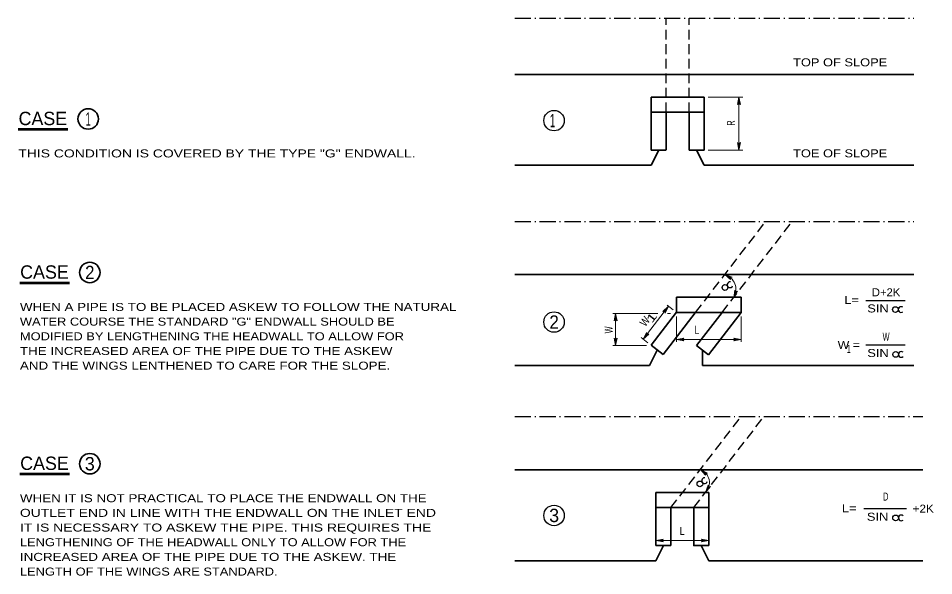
# Model space of a CAD drawing. Extents: x 134 to 247, y -59 to 103.
# Drawn here: x 133.6 to 246.8, y 34.2 to 103.1 of the extents above; entities that cross this region are included whole.
import ezdxf
from ezdxf.enums import TextEntityAlignment as Align

# ---------------------------------------------------------------- set-up
doc = ezdxf.new("R2010")
doc.units = 0
doc.header["$LTSCALE"] = 0.4
doc.linetypes.add('DOT_DASHED', pattern=[7.7, 5, -1.2, 0.3, -1.2])
doc.linetypes.add('MEDIUM_DASHED', pattern=[4.5, 3, -1.5])
for name, color, linetype, lineweight in [('1', 7, 'Continuous', 35), ('10', 7, 'Continuous', 13), ('13', 7, 'Continuous', 53)]:
    doc.layers.add(name, color=color, linetype=linetype, lineweight=lineweight)
doc.layers.add('12', color=7, linetype='Continuous')

msp = doc.modelspace()

# ---------------------------------------------------------------- linework, layer by layer
at = {"layer": '1', "linetype": 'DOT_DASHED', "lineweight": 25}
for p, q in [((194.9967, 103.1357), (244.3561, 103.1357)), ((194.9967, 78.0264), (244.3561, 78.0264)), ((194.9967, 53.876), (245.4598, 53.876))]:
    msp.add_line(p, q, dxfattribs=at)
at = {"layer": '1', "linetype": 'MEDIUM_DASHED', "lineweight": 25}
for p, q in [((213.7467, 91.5186), (213.7467, 103.1357)), ((216.5592, 91.5186), (216.5592, 103.1357)), ((217.3504, 66.7439), (226.0509, 78.0264)), ((220.6394, 66.7439), (229.3399, 78.0264)), ((214.324, 42.626), (223.0245, 53.9086)), ((217.1365, 42.626), (225.837, 53.9086))]:
    msp.add_line(p, q, dxfattribs=at)
at = {"layer": '1'}
for p, q in [((194.9967, 96.2061), (244.3561, 96.2061)), ((211.8717, 93.3936), (218.4342, 93.3936)), ((211.8717, 93.3936), (211.8717, 86.8311)), ((218.4342, 93.3936), (218.4342, 86.8311)), ((211.8717, 91.5186), (218.4342, 91.5186)), ((213.7467, 91.5186), (213.7467, 86.8534)), ((216.5592, 91.5186), (216.5592, 86.8311)), ((211.8717, 86.8311), (213.7467, 86.8311)), ((212.8092, 86.8311), (211.8717, 84.9561)), ((216.5592, 86.8311), (218.4342, 86.8311)), ((217.4967, 86.8311), (218.4342, 84.9561)), ((194.9967, 84.9561), (211.8717, 84.9561)), ((218.4342, 84.9561), (244.3561, 84.9561)), ((194.9967, 71.4639), (244.3561, 71.4639)), ((214.9949, 68.6684), (223.0071, 68.6684)), ((214.9949, 66.7439), (214.9949, 68.6684)), ((223.0071, 66.7439), (223.0071, 68.6684)), ((211.8677, 62.7045), (215.0077, 66.7764)), ((213.3525, 61.5596), (217.3194, 66.7038)), ((214.9949, 66.7439), (223.0071, 66.7439)), ((217.4913, 62.6614), (220.6545, 66.7634)), ((218.976, 61.5164), (223.0071, 66.7439)), ((211.8677, 62.7046), (213.3525, 61.5596)), ((217.4913, 62.6614), (218.9761, 61.5164)), ((212.6087, 62.0889), (211.6712, 60.2139)), ((218.2337, 62.0889), (218.2337, 60.2139)), ((194.9967, 60.2139), (211.6712, 60.2139)), ((218.2337, 60.2139), (244.3561, 60.2139)), ((194.9967, 47.3135), (245.4598, 47.3135)), ((212.449, 44.501), (219.0115, 44.501)), ((212.449, 44.501), (212.449, 37.9385)), ((219.0115, 44.501), (219.0115, 37.9385)), ((212.449, 42.626), (219.0115, 42.626)), ((214.324, 42.626), (214.324, 37.9608)), ((212.449, 37.9385), (214.324, 37.9385)), ((213.3865, 37.9385), (212.449, 36.0635)), ((218.074, 37.9385), (219.0115, 36.0635)), ((194.9967, 36.0635), (212.449, 36.0635)), ((219.0115, 36.0635), (245.4598, 36.0635))]:
    msp.add_line(p, q, dxfattribs=at)
msp.add_lwpolyline([(217.1365, 42.626), (217.1365, 37.9385), (219.0115, 37.9385)], dxfattribs=at)
at = {"layer": '10'}
for p, q in [((218.9342, 93.3936), (223.2237, 93.3936)), ((222.7237, 93.3936), (222.7237, 86.8311)), ((218.9342, 86.8311), (223.2237, 86.8311)), ((210.8773, 63.4553), (214.0173, 67.5272)), ((214.6118, 67.0818), (213.8622, 67.6598)), ((207.1474, 66.6484), (212.6528, 66.6484)), ((207.4808, 66.6484), (207.4808, 62.6583)), ((212.4055, 66.6484), (212.7147, 66.6484)), ((213.8894, 66.6484), (214.2706, 66.6484)), ((214.9949, 66.2439), (214.9949, 63.1132)), ((223.0071, 66.2439), (223.0071, 63.1132)), ((211.4718, 63.0099), (210.6185, 63.6678)), ((214.9949, 63.4257), (223.0071, 63.4257)), ((207.1474, 62.6583), (211.3029, 62.6583)), ((212.449, 38.558), (219.0115, 38.558))]:
    msp.add_line(p, q, dxfattribs=at)
at = {"layer": '10', "lineweight": 25}
for p, q in [((238.4025, 68.2561), (243.2971, 68.2561)), ((238.4025, 62.7465), (243.2971, 62.7465)), ((238.1672, 42.4974), (243.4383, 42.4974))]:
    msp.add_line(p, q, dxfattribs=at)
at = {"layer": '10'}
for points in [[(222.7237, 93.3936), (222.8984, 92.4615), (222.8487, 92.5333), (222.7862, 92.5704), (222.7237, 92.5811), (222.6612, 92.5704), (222.5987, 92.5333), (222.5489, 92.4615), (222.7237, 93.3936), (222.5987, 92.5333), (222.6612, 92.5704), (222.7237, 93.3936), (222.7237, 92.5811), (222.7862, 92.5704), (222.7237, 93.3936), (222.8487, 92.5333)], [(222.7237, 86.8311), (222.5489, 87.7631), (222.5987, 87.6913), (222.6612, 87.6543), (222.7237, 87.6436), (222.7862, 87.6543), (222.8487, 87.6913), (222.8984, 87.7631), (222.7237, 86.8311), (222.8487, 87.6913), (222.7862, 87.6543), (222.7237, 86.8311), (222.7237, 87.6436), (222.6612, 87.6543), (222.7237, 86.8311), (222.5987, 87.6913)], [(220.9857, 71.4684), (221.8696, 71.1248), (221.7824, 71.1204), (221.7179, 71.0869), (221.6758, 71.0395), (221.6519, 70.9807), (221.6504, 70.9081), (221.6851, 70.8279), (220.9857, 71.4684), (221.6504, 70.9081), (221.6519, 70.9807), (220.9857, 71.4684), (221.6758, 71.0395), (221.7179, 71.0869), (220.9857, 71.4684), (221.7824, 71.1204)], [(222.1022, 68.5733), (222.2095, 69.5156), (222.2359, 69.4323), (222.2848, 69.3785), (222.3413, 69.3498), (222.4042, 69.3417), (222.4749, 69.3587), (222.5436, 69.4127), (222.1022, 68.5733), (222.4749, 69.3587), (222.4042, 69.3417), (222.1022, 68.5733), (222.3413, 69.3498), (222.2848, 69.3785), (222.1022, 68.5733), (222.2359, 69.4323)], [(214.0173, 67.5272), (213.5865, 66.6824), (213.591, 66.7696), (213.5641, 66.8371), (213.5211, 66.8838), (213.4651, 66.9135), (213.393, 66.9223), (213.3097, 66.8958), (214.0173, 67.5272), (213.393, 66.9223), (213.4651, 66.9135), (214.0173, 67.5272), (213.5211, 66.8838), (213.5641, 66.8371), (214.0173, 67.5272), (213.591, 66.7696)], [(207.4808, 66.6484), (207.6555, 65.7164), (207.6058, 65.7882), (207.5433, 65.8252), (207.4808, 65.8359), (207.4183, 65.8252), (207.3558, 65.7882), (207.306, 65.7164), (207.4808, 66.6484), (207.3558, 65.7882), (207.4183, 65.8252), (207.4808, 66.6484), (207.4808, 65.8359), (207.5433, 65.8252), (207.4808, 66.6484), (207.6058, 65.7882)], [(207.4808, 62.6583), (207.306, 63.5904), (207.3558, 63.5185), (207.4183, 63.4815), (207.4808, 63.4708), (207.5433, 63.4815), (207.6058, 63.5185), (207.6555, 63.5904), (207.4808, 62.6583), (207.6058, 63.5185), (207.5433, 63.4815), (207.4808, 62.6583), (207.4808, 63.4708), (207.4183, 63.4815), (207.4808, 62.6583), (207.3558, 63.5185)], [(210.8773, 63.4553), (211.3081, 64.3001), (211.3036, 64.2128), (211.3305, 64.1453), (211.3734, 64.0987), (211.4295, 64.069), (211.5016, 64.0602), (211.5848, 64.0866), (210.8773, 63.4553), (211.5016, 64.0602), (211.4295, 64.069), (210.8773, 63.4553), (211.3734, 64.0987), (211.3305, 64.1453), (210.8773, 63.4553), (211.3036, 64.2128)], [(214.9949, 63.4257), (215.927, 63.6005), (215.8552, 63.5507), (215.8181, 63.4882), (215.8074, 63.4257), (215.8181, 63.3632), (215.8552, 63.3007), (215.927, 63.251), (214.9949, 63.4257), (215.8552, 63.3007), (215.8181, 63.3632), (214.9949, 63.4257), (215.8074, 63.4257), (215.8181, 63.4882), (214.9949, 63.4257), (215.8552, 63.5507)], [(223.0071, 63.4257), (222.0751, 63.251), (222.1469, 63.3007), (222.1839, 63.3632), (222.1946, 63.4257), (222.1839, 63.4882), (222.1469, 63.5507), (222.0751, 63.6005), (223.0071, 63.4257), (222.1469, 63.5507), (222.1839, 63.4882), (223.0071, 63.4257), (222.1946, 63.4257), (222.1839, 63.3632), (223.0071, 63.4257), (222.1469, 63.3007)], [(217.9705, 47.3238), (218.8199, 46.9021), (218.7325, 46.9056), (218.6653, 46.878), (218.6192, 46.8346), (218.5901, 46.7782), (218.582, 46.706), (218.6094, 46.623), (217.9705, 47.3238), (218.582, 46.706), (218.5901, 46.7782), (217.9705, 47.3238), (218.6192, 46.8346), (218.6653, 46.878), (217.9705, 47.3238), (218.7325, 46.9056)], [(218.5935, 44.5053), (218.9147, 45.3976), (218.9212, 45.3105), (218.9564, 45.2469), (219.0049, 45.206), (219.0642, 45.1836), (219.1368, 45.1839), (219.2161, 45.2207), (218.5935, 44.5053), (219.1368, 45.1839), (219.0642, 45.1836), (218.5935, 44.5053), (219.0049, 45.206), (218.9564, 45.2469), (218.5935, 44.5053), (218.9212, 45.3105)], [(212.449, 38.558), (213.3811, 38.7327), (213.3093, 38.683), (213.2722, 38.6205), (213.2615, 38.558), (213.2722, 38.4955), (213.3093, 38.433), (213.3811, 38.3832), (212.449, 38.558), (213.3093, 38.433), (213.2722, 38.4955), (212.449, 38.558), (213.2615, 38.558), (213.2722, 38.6205), (212.449, 38.558), (213.3093, 38.683)], [(212.449, 38.558), (213.3811, 38.7327), (213.3093, 38.683), (213.2722, 38.6205), (213.2615, 38.558), (213.2722, 38.4955), (213.3093, 38.433), (213.3811, 38.3832), (212.449, 38.558), (213.3093, 38.433), (213.2722, 38.4955), (212.449, 38.558), (213.2615, 38.558), (213.2722, 38.6205), (212.449, 38.558), (213.3093, 38.683)], [(219.0115, 38.558), (218.0794, 38.3832), (218.1513, 38.433), (218.1883, 38.4955), (218.199, 38.558), (218.1883, 38.6205), (218.1513, 38.683), (218.0794, 38.7327), (219.0115, 38.558), (218.1513, 38.683), (218.1883, 38.6205), (219.0115, 38.558), (218.199, 38.558), (218.1883, 38.4955), (219.0115, 38.558), (218.1513, 38.433)]]:
    msp.add_lwpolyline(points, dxfattribs=at)
at = {"layer": '10', "lineweight": 35}
for centre in [(142.2558, 90.6883), (142.4553, 71.7032), (142.4564, 48.0533)]:
    msp.add_circle(centre, 1.2661, dxfattribs=at)
at = {"layer": '10', "lineweight": 25}
for centre, radius in [((199.8638, 90.487), 1.2661), ((220.9988, 69.8467), 0.3542), ((199.8638, 65.5745), 1.2661), ((242.073, 67.1216), 0.3542), ((242.1071, 61.5693), 0.3542), ((217.8958, 45.5535), 0.3542), ((199.8638, 41.6581), 1.2661), ((242.1008, 41.3514), 0.3542)]:
    msp.add_circle(centre, radius, dxfattribs=at)
at = {"layer": '10'}
for centre, radius, start, end in [((220.388, 69.5923), 1.9661, 329.87836, 72.16387), ((217.3764, 45.7049), 1.7041, 315.05105, 70.72989)]:
    msp.add_arc(centre, radius, start, end, dxfattribs=at)
at = {"layer": '10', "lineweight": 25}
for centre, start, end in [((221.6208, 70.1858), 79.03113, 338.16146), ((242.7814, 67.1216), 50.43484, 309.56516), ((242.8155, 61.5693), 50.43484, 309.56516), ((218.4724, 45.9651), 85.95524, 345.08557), ((242.8092, 41.3514), 50.43484, 309.56516)]:
    msp.add_arc(centre, 0.3542, start, end, dxfattribs=at)
at = {"layer": '13'}
for p, q in [((133.6162, 89.4222), (139.7558, 89.4222)), ((133.8158, 70.4371), (139.9553, 70.4371)), ((133.8169, 46.7872), (139.9564, 46.7872))]:
    msp.add_line(p, q, dxfattribs=at)

# ---------------------------------------------------------------- texts
at = {"layer": '12', "width": 1.2}
for s, p in [('TOP OF SLOPE', (229.4158, 97.1958)), ('TOE OF SLOPE', (229.4158, 85.9458))]:
    msp.add_text(s, height=0.99, dxfattribs=at).set_placement(p)
at = {"layer": '12'}
for s, rotation, width, p in [('R', 90, 0.7, (222.2187, 90.1819)), ('W', 52.362, 0.85, (211.4756, 65.3443)), ('1', 52.362, 1.6, (212.3145, 65.8258)), ('W', 90, 0.6, (207.1206, 64.6038))]:
    msp.add_text(s, height=0.99, rotation=rotation, dxfattribs=dict(at, width=width)).set_placement(p, align=Align.CENTER)
for s, width, p in [('D+2K', 1.05, (240.9194, 68.7611)), ('L=', 1.2, (236.6592, 67.8011)), ('SIN', 1.2, (239.9194, 66.7611)), ('L', 0.85, (217.5051, 64.1257)), ('W', 0.6, (240.9194, 63.2515)), ('W =', 1.15, (236.3079, 62.2488)), ('1', 0.55, (236.3079, 61.7488)), ('SIN', 1.2, (239.9194, 61.2515)), ('D', 0.7, (240.8723, 43.4974)), ('L=', 1.2, (236.3538, 42.0616)), ('SIN', 1.2, (239.8723, 41.0024)), ('+2K', 1.1, (245.5079, 42.0024)), ('L', 0.85, (215.7038, 39.258))]:
    msp.add_text(s, height=0.99, dxfattribs=dict(at, width=width)).set_placement(p, align=Align.CENTER)
at = {"layer": '13'}
for s, p in [('CASE', (136.6515, 89.9222)), ('CASE', (136.8511, 70.9371)), ('CASE', (136.8522, 47.2872)), ('3', (142.4564, 47.2283)), ('3', (199.8718, 40.8331))]:
    msp.add_text(s, height=1.65, dxfattribs=at).set_placement(p, align=Align.CENTER)
for s, width, p in [('1', 0.55, (142.2558, 89.8633)), ('1', 0.55, (199.6795, 89.662)), ('2', 0.95, (142.4553, 70.8782)), ('2', 0.95, (199.8701, 64.7495))]:
    msp.add_text(s, height=1.65, dxfattribs=dict(at, width=width)).set_placement(p, align=Align.CENTER)
for s, width, p in [('THIS CONDITION IS COVERED BY THE TYPE "G" ENDWALL.', 1.3, (133.6162, 85.9322)), ('WHEN A PIPE IS TO BE PLACED ASKEW TO FOLLOW THE NATURAL', 1.25, (133.8158, 66.9471)), ('WATER COURSE THE STANDARD "G" ENDWALL SHOULD BE', 1.2, (133.8158, 65.1321)), ('MODIFIED BY LENGTHENING THE HEADWALL TO ALLOW FOR', 1.2, (133.8158, 63.3171)), ('THE INCREASED AREA OF THE PIPE DUE TO THE ASKEW', 1.25, (133.8158, 61.5021)), ('AND THE WINGS LENTHENED TO CARE FOR THE SLOPE.', 1.25, (133.8158, 59.6871)), ('WHEN IT IS NOT PRACTICAL TO PLACE THE ENDWALL ON THE', 1.25, (133.8169, 43.2972)), ('OUTLET END IN LINE WITH THE ENDWALL ON THE INLET END', 1.3, (133.8169, 41.4822)), ('IT IS NECESSARY TO ASKEW THE PIPE. THIS REQUIRES THE', 1.3, (133.8169, 39.6672)), ('LENGTHENING OF THE HEADWALL ONLY TO ALLOW FOR THE', 1.2, (133.8169, 37.8522)), ('INCREASED AREA OF THE PIPE DUE TO THE ASKEW. THE', 1.25, (133.8169, 36.0372)), ('LENGTH OF THE WINGS ARE STANDARD.', 1.2, (133.8169, 34.2222))]:
    msp.add_text(s, height=0.99, dxfattribs=dict(at, width=width)).set_placement(p)

doc.saveas('drawing.dxf')
